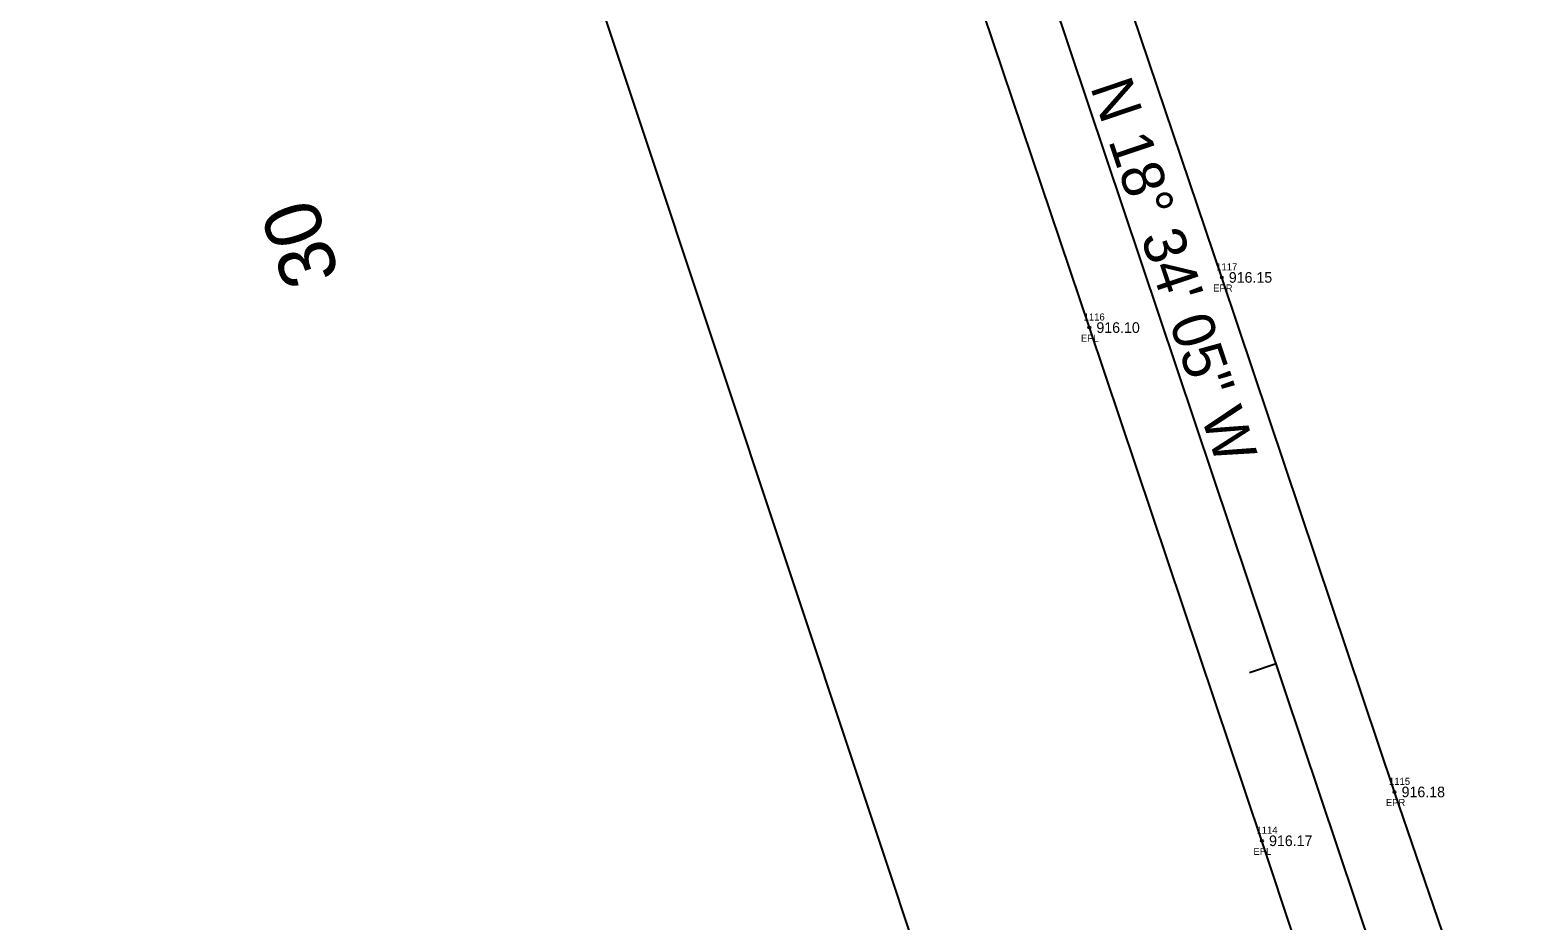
# Model space of a CAD drawing. Extents: x 1528109 to 1531398, y 1157799 to 1162548.
# Drawn here: x 1529562.7 to 1529775.9, y 1159971 to 1160096.9 of the extents above; entities that cross this region are included whole.
import ezdxf

# ---------------------------------------------------------------- set-up
doc = ezdxf.new("R2010")
doc.units = 0
for name, color, linetype in [('RD_EX_Road', 7, 'Continuous'), ('RD_EX_Road_txCode', 7, 'Continuous'), ('RD_EX_TX_Road_ELEV', 7, 'Continuous'), ('RD_EX_VEG', 7, 'Continuous'), ('RD_HC_Cl', 7, 'Continuous'), ('RD_HC_Data', 7, 'Continuous'), ('RD_HC_Data_Tic', 7, 'Continuous'), ('RD_HC_TX_Sta50', 7, 'Continuous'), ('RD_SMD_Locator', 7, 'Continuous')]:
    doc.layers.add(name, color=color, linetype=linetype)

msp = doc.modelspace()

# ---------------------------------------------------------------- linework, layer by layer
at = {"layer": 'RD_EX_Road'}
for points in [[(1529774.72, 1159933.62), (1529755.68, 1159989.25), (1529731.24, 1160061.98), (1529709.49, 1160126.43), (1529696.87, 1160163.6), (1529690.11, 1160182.42), (1529676.19, 1160223.82)], [(1529755.29, 1159927.01), (1529736.93, 1159982.35), (1529712.51, 1160054.89), (1529690.79, 1160119.37), (1529677.8, 1160158.1), (1529657.44, 1160217.45)]]:
    msp.add_lwpolyline(points, dxfattribs=at)
at = {"layer": 'RD_EX_VEG'}
msp.add_lwpolyline([(1529518.34, 1160217.08), (1529606.49, 1160211.39), (1529711.98, 1159894.63), (1529689.16, 1159889.01)], dxfattribs=at)
at = {"layer": 'RD_HC_Cl'}
msp.add_line((1529913.5, 1159487.74), (1529527.85, 1160635.77), dxfattribs=at)
at = {"layer": 'RD_HC_Data_Tic'}
msp.add_line((1529738.94, 1160007.38), (1529735.15, 1160006.11), dxfattribs=at)
at = {"layer": 'RD_SMD_Locator'}
for centre in [(1529731.24, 1160061.98), (1529712.51, 1160054.89), (1529755.68, 1159989.25), (1529736.93, 1159982.35)]:
    msp.add_circle(centre, 0.15, dxfattribs=at)

# ---------------------------------------------------------------- texts
at = {"layer": 'RD_EX_Road_txCode'}
for s, p in [('1117', (1529730.46, 1160062.98)), ('EPR', (1529730.02, 1160059.98)), ('1116', (1529711.71, 1160055.89)), ('EPL', (1529711.31, 1160052.89)), ('1115', (1529754.9, 1159990.25)), ('EPR', (1529754.45, 1159987.25)), ('1114', (1529736.15, 1159983.35)), ('EPL', (1529735.72, 1159980.35))]:
    msp.add_text(s, height=1, dxfattribs=at).set_placement(p)
at = {"layer": 'RD_EX_TX_Road_ELEV'}
for s, p in [('916.15', (1529732.24, 1160061.23)), ('916.10', (1529713.51, 1160054.14)), ('916.18', (1529756.68, 1159988.5)), ('916.17', (1529737.93, 1159981.6))]:
    msp.add_text(s, height=1.5, dxfattribs=at).set_placement(p)
at = {"layer": 'RD_HC_Data'}
msp.add_text('N 18%%d 34\' 05" W', height=6, rotation=288.568, dxfattribs=at).set_placement((1529712.6, 1160088.92))
at = {"layer": 'RD_HC_TX_Sta50'}
msp.add_text('30', height=8, rotation=108.568, dxfattribs=at).set_placement((1529606.56, 1160062.29))

doc.saveas('drawing.dxf')
